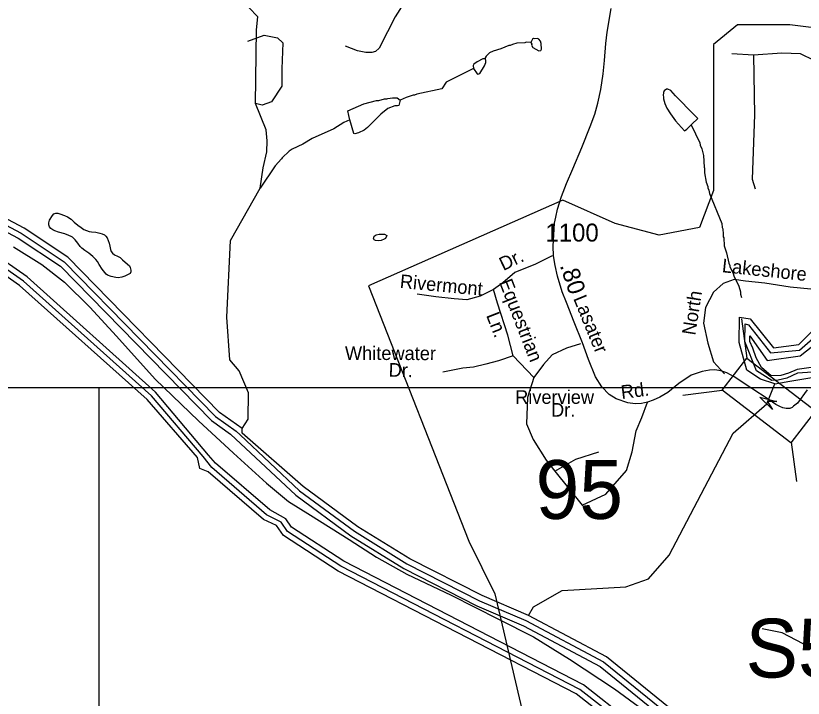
# Model space of a CAD drawing. Extents: x 1547597 to 1699558, y 810033 to 920809.
# Drawn here: x 1574920 to 1580417, y 829140 to 833901 of the extents above; entities that cross this region are included whole.
import ezdxf

# ---------------------------------------------------------------- set-up
doc = ezdxf.new("R2010")
doc.units = 0
for name, color, linetype in [('Exist Boundary Political City Limit New', 7, 'Continuous'), ('Exist Boundary Political CountyLine', 7, 'Continuous'), ('Exist Hydrographic Bay Label', 7, 'Continuous'), ('Exist Hydrographic Buffer Line', 7, 'Continuous'), ('Exist Hydrographic Creek Single Shore', 7, 'Continuous'), ('Exist Hydrographic Lake Shore', 7, 'Continuous'), ('Exist Hydrographic Misc Water Feature', 7, 'Continuous'), ('Exist Road Non-System Type 51', 7, 'Continuous'), ('Exist Road Non-System Type 51 Label', 7, 'Continuous'), ('Exist Road Primary Interstate Structure Ovrhead Sign Number Label', 7, 'Continuous'), ('Exist Road Secondary Mileage Hundredths English Label', 7, 'Continuous'), ('Exist Road Secondary Structure Standard Bridge Attributed CELL', 7, 'Continuous'), ('Exist Road Secondary Structure Standard Bridge CELL', 7, 'Continuous'), ('Exist Road Secondary Structure Standard Bridge Number Label', 7, 'Continuous'), ('Exist Road Secondary Type 51 Attributed', 7, 'Continuous'), ('Exist Road Secondary Type 51 Label', 7, 'Continuous'), ('Exist Road Secondary Type 51 Number Label', 7, 'Continuous'), ('Map Preparation Boundary City Limit Buffer Line', 7, 'Continuous'), ('Map Preparation Inset Cut Line', 7, 'Continuous')]:
    doc.layers.add(name, color=color, linetype=linetype)

msp = doc.modelspace()

# ---------------------------------------------------------------- linework, layer by layer
at = {"layer": 'Exist Boundary Political City Limit New'}
msp.add_lwpolyline([(1580658, 833796.5), (1580321.9, 833837.3), (1579957.7, 833837.3), (1579789.6, 833701.4), (1579789.6, 832682), (1579691.5, 832423.7), (1579411.4, 832369.4), (1579103.2, 832450.9), (1578739, 832614), (1577381.7, 832016), (1578082.1, 830235.4), (1578264.2, 829868.4), (1578460.3, 829033.8), (1578866.5, 827796.9), (1579062.6, 826940.6), (1579272.7, 826560), (1579538.9, 825894), (1580015.1, 826233.8), (1580561.4, 826641.6)], dxfattribs=at)
at = {"layer": 'Exist Boundary Political CountyLine'}
msp.add_lwpolyline([(1574903.6, 832288.8), (1575102.3, 832165.2), (1575261.2, 832041.5), (1575437.8, 831869.2), (1575623.2, 831666.1), (1575892.4, 831365.7), (1576197, 831074.2), (1576439.8, 830849), (1576669.4, 830641.4), (1576823.9, 830513.3), (1576978.4, 830416.1), (1577247.7, 830248.3), (1577437.5, 830124.6), (1577649.4, 830005.3), (1577958.4, 829859.6), (1578289.5, 829691.8), (1578534.5, 829568.1), (1578786.2, 829413.5), (1579099.6, 829205.9), (1579368.9, 829007.2)], dxfattribs=at)
at = {"layer": 'Exist Hydrographic Bay Label'}
for points in [[(1576500.5, 831022.5), (1576343.5, 831134), (1575283.5, 832215.8), (1574978.5, 832419), (1574167.5, 832849), (1573820.5, 833112.1), (1573485.5, 833516.1), (1573216.5, 833981.1), (1573152.5, 834162.9), (1573095.5, 834233.1), (1572740.5, 835060.9), (1572605.5, 835523.3), (1572580.5, 835540.2), (1572581.4, 835589.4), (1572371.5, 836049.9), (1572346.4, 836060.3), (1572330.5, 836119.7), (1572158.5, 836330), (1571821.5, 836658.5), (1571434.5, 836958.5), (1570908.5, 837497.8), (1570744.5, 837724.2)], [(1576204.5, 830743), (1576188.5, 830818.8), (1575836.5, 831223.1), (1574947.5, 832019.1), (1574699.5, 832191.6), (1574120.5, 832498.7), (1573815.4, 832728.1), (1573659.5, 832888.9), (1573080.5, 833757.4), (1572731.4, 834480.1), (1572529.5, 834864.9), (1572400.5, 835176.2), (1572409.5, 835208.8), (1572360.5, 835285.3), (1572353.5, 835383.9), (1572134.5, 835854.5), (1571963.5, 836091), (1571642.5, 836412.6), (1571132.4, 836843.2), (1570959.5, 837020.7), (1570893.5, 837048.3)], [(1578498.5, 829718.2), (1578175.5, 829856.1), (1577671.5, 830112.5), (1577307.5, 830336.5), (1576927.5, 830616.7), (1576499.5, 830989.7), (1576500.5, 831022.5)], [(1580668.5, 826375.2), (1580662.5, 826559.1), (1580637.5, 826592.5), (1580565.6, 827335.8), (1580330.6, 827832.9), (1580035.5, 828186.9), (1579780.5, 828408.7), (1579524.5, 828578), (1579146.5, 828923.9), (1578832.6, 829169.8), (1577169.5, 830027.5), (1576789.5, 830274.8), (1576740.5, 830344.7), (1576649.5, 830385.9), (1576262.5, 830718.8), (1576204.5, 830743)], [(1581965.5, 823873.7), (1581867.5, 824016.9), (1581706.6, 824378), (1581658.6, 824520.1), (1581561.5, 824722.3), (1581505.5, 824930.2), (1581481.5, 824947.2), (1581281.5, 825574.9), (1581208.5, 825717.5), (1581026.5, 826338.4), (1580929.5, 827157.8), (1580890.6, 827322.6), (1580647.6, 827852.8), (1580418.5, 828139.8), (1579786.6, 828825.5), (1579044.5, 829428.1), (1578498.5, 829718.2)]]:
    msp.add_lwpolyline(points, dxfattribs=at)
at = {"layer": 'Exist Hydrographic Buffer Line'}
for points in [[(1574119.2, 832785.3), (1574937.5, 832350.2), (1575232.2, 832153.8), (1576286.4, 831078), (1576420.2, 830981.4), (1576874.9, 830556.4), (1577260, 830272.1), (1577629.6, 830044.4), (1578139.2, 829784.8), (1578464, 829646), (1579000.1, 829361.1), (1579731.6, 828767.1)], [(1574143.3, 832817.1), (1574958, 832384.6), (1575257.9, 832184.9), (1576314.9, 831106), (1576459.9, 831002.3), (1576487.2, 830976.6), (1576901.3, 830586.5), (1577283.7, 830304.3), (1577650.6, 830078.4), (1578157.3, 829820.5), (1578481.3, 829682), (1579022.2, 829394.6), (1579759.1, 828796.3)], [(1579200.5, 828982.9), (1578881.9, 829232.8), (1577209.8, 830096.7), (1576846.1, 830333.3), (1576806, 830390.6), (1576692.9, 830454.1), (1576314.7, 830779.4), (1576266.7, 830835.3), (1575896.9, 831275.7), (1575001, 832078.7), (1574745.1, 832257.2)], [(1580198, 831356.6), (1580090.5, 831424.5), (1580008.6, 831628.1), (1580010.8, 831752.8), (1580034, 831745.5), (1580189.1, 831548.6), (1580390.6, 831567.3), (1580501.3, 831665), (1580877.9, 831641.1), (1580979.7, 831760.3), (1581012.9, 831926.1), (1580974.6, 832128.1), (1580976, 832227.9), (1581049.7, 832160.8), (1581086.4, 832039.6), (1581115.9, 831831.9)], [(1579173.5, 828953.4), (1578857.3, 829201.3), (1577189.6, 830062.1), (1576817.8, 830304), (1576773.3, 830367.7), (1576671.2, 830420), (1576288.6, 830749.1), (1576227.7, 830827.1), (1575866.7, 831249.4), (1574974.2, 832048.9), (1574722.4, 832224.4)], [(1580567.6, 831462.2), (1580373.4, 831432.9), (1580313.2, 831407.4), (1580259.6, 831392.2), (1580191.8, 831390.1), (1580125, 831446.5), (1580088.3, 831514.8), (1580063.8, 831581.4), (1580042.9, 831629.1), (1580042.9, 831667.9), (1580165.2, 831494.9), (1580395.8, 831527.6), (1580516, 831623.4)], [(1580585.3, 831421.4), (1580375.6, 831406.7), (1580301.4, 831373.3), (1580241.9, 831358.7), (1580198, 831356.6)]]:
    msp.add_lwpolyline(points, dxfattribs=at)
at = {"layer": 'Exist Hydrographic Creek Single Shore'}
for points in [[(1576500.5, 831022.5), (1576542.5, 831087.4), (1576545.5, 831271.1), (1576480.5, 831423.5), (1576415.5, 831500.2), (1576394.5, 831799.4), (1576419.5, 832334), (1576625.4, 832698.5), (1576646.4, 832841), (1576673.7, 832952.2), (1576675.7, 833028.2), (1576667.9, 833106.2), (1576593.2, 833289.3), (1576600.6, 833803.4), (1576610.3, 833893.1), (1576547.9, 833957.5), (1576498.7, 834080.8), (1576483.8, 834208.9)], [(1578498.5, 829718.2), (1578533.5, 829776.6), (1578734.5, 829890.7), (1579177.6, 829917.8), (1579336.6, 829973.7), (1579480.5, 830138.2), (1579926.5, 830989.3), (1580162.5, 831194.6), (1580218.9, 831333.6)]]:
    msp.add_lwpolyline(points, dxfattribs=at)
at = {"layer": 'Exist Hydrographic Lake Shore'}
for points in [[(1580218.9, 831333.6), (1580271.1, 831343), (1580308.7, 831350.4), (1580365.1, 831358.7), (1580475.7, 831376.5), (1580595.7, 831389), (1580838.6, 831259.6), (1581047.5, 831291.5), (1581301.5, 831519.5), (1581494.5, 831591.1), (1581710.6, 831590), (1581726.6, 831556.8), (1581918.5, 831536.5), (1582145.6, 831673.1), (1582306.5, 831863.5), (1582542.6, 832003.2), (1582751.5, 832074.4), (1582828.5, 832214), (1582980.6, 832378.3), (1582991.5, 832538.9)], [(1580218.9, 831333.6), (1580117.7, 831366), (1580023.7, 831427.7), (1579968.5, 831621.9), (1579971.5, 831799.2), (1580046.6, 831787.8), (1580209.5, 831584.3), (1580385.5, 831607), (1580486.5, 831706.6)]]:
    msp.add_lwpolyline(points, dxfattribs=at)
at = {"layer": 'Exist Hydrographic Misc Water Feature'}
for points in [[(1576539.4, 833724), (1576654.7, 833766.3), (1576746.9, 833747), (1576785.3, 833712.4), (1576777.7, 833531.7), (1576777.7, 833408.6), (1576704.6, 833300.9), (1576639.3, 833277.8), (1576593.2, 833289.3)], [(1578514.7, 833713.8), (1578482.7, 833716.2), (1578474.6, 833712.3), (1578418.7, 833709.1), (1578386.6, 833701.5), (1578370.5, 833693.7), (1578362.5, 833693.8), (1578306.2, 833670.5), (1578252.1, 833653.2), (1578227.9, 833641.5), (1578203.7, 833619.8), (1578195.5, 833607.9), (1578197.4, 833599.9)], [(1578514.7, 833713.8), (1578522.5, 833703.8), (1578520.5, 833695.8), (1578528.3, 833679.7), (1578570, 833655.2), (1578586, 833659), (1578590.1, 833666.9), (1578586.6, 833707), (1578582.8, 833723), (1578570.9, 833737.2), (1578563, 833741.3), (1578543, 833739.5), (1578535, 833741.6), (1578526.9, 833737.7), (1578514.7, 833713.8)], [(1578197.4, 833599.9), (1578181.4, 833600.1), (1578141.2, 833580.6), (1578117, 833562.9), (1578112.9, 833555), (1578114.3, 833532.3)], [(1578114.3, 833532.3), (1578140.2, 833496.7), (1578146.1, 833492.6), (1578160.2, 833498.4), (1578192.8, 833552), (1578201.1, 833575.9), (1578201.3, 833591.8), (1578197.4, 833599.9)], [(1578114.3, 833532.3), (1577925.5, 833437.4), (1577895, 833391.8), (1577718.6, 833354), (1577702.5, 833346.2), (1577694.5, 833346.3), (1577646.3, 833330.9), (1577604, 833313)], [(1579634.4, 833140.5), (1579639.6, 833144), (1579680.1, 833183.5), (1579654.4, 833209.8), (1579526, 833341.3), (1579492.5, 833379.7), (1579470.6, 833388), (1579462.6, 833388.1), (1579446.5, 833376.3), (1579440.3, 833366.4), (1579438.1, 833344.4), (1579442, 833336.4), (1579441.8, 833320.4), (1579449.5, 833288.3), (1579465, 833256.1), (1579490.6, 833215.8), (1579525.9, 833167.4), (1579588.9, 833098), (1579603.2, 833110.5), (1579634.4, 833140.5)], [(1577251.9, 833174.3), (1577244.9, 833204), (1577237.2, 833236.8), (1577349.8, 833286.7), (1577438.1, 833309.6), (1577454.1, 833309.4), (1577494.3, 833320.9), (1577510.3, 833320.6), (1577518.3, 833324.5), (1577550.3, 833328.1), (1577582.4, 833327.8), (1577604, 833313)], [(1577604, 833313), (1577593.6, 833275.6), (1577583.7, 833271.7), (1577565.6, 833272), (1577517.5, 833254.6), (1577469, 833215.2), (1577375.9, 833120.4), (1577351.7, 833102.7), (1577311.5, 833083.2), (1577287.4, 833077.6), (1577279.4, 833079.7), (1577251.9, 833174.3)], [(1577251.9, 833174.3), (1577210.4, 833156.5), (1577139.8, 833111.4), (1576989, 833045.3), (1576924.6, 833006.1), (1576850.2, 832971.1), (1576828.1, 832957.4), (1576779.5, 832910), (1576775.5, 832902.1), (1576730.9, 832854.7), (1576625.4, 832698.5)], [(1579634.4, 833140.5), (1579694.1, 833013.4), (1579697.9, 832997.3), (1579709.7, 832973.2), (1579721, 832925), (1579724.1, 832845), (1579728, 832837), (1579727.6, 832805), (1579738.9, 832740.9), (1579750.5, 832708.8), (1579750.4, 832700.8), (1579758.2, 832684.7), (1579762, 832660.6), (1579847.5, 832451.7), (1579851, 832423.6), (1579854.9, 832415.6), (1579854.8, 832399.6), (1579858.7, 832391.6), (1579858.3, 832359.6), (1579862.2, 832351.5), (1579865.6, 832295.5), (1579881, 832247.4), (1579896.2, 832175.2), (1579904, 832159.1), (1579903.8, 832151.1), (1579927.2, 832102.8), (1579931.1, 832086.8), (1579966.2, 832014.4), (1579977.8, 831974.3), (1579977.6, 831958.3), (1579984.7, 831936.5)], [(1575542, 832109), (1575524.1, 832133.5), (1575503.1, 832165.9), (1575490.4, 832186.4), (1575478.9, 832201), (1575457.7, 832221.6), (1575430.6, 832243.6), (1575403.6, 832264.4), (1575381, 832280.5), (1575369.4, 832291.7), (1575354.8, 832313.6), (1575334.3, 832338.1), (1575316.3, 832355.4), (1575306.6, 832361.5), (1575291.1, 832368.9), (1575263.1, 832378.6), (1575218.9, 832391.8), (1575193, 832400.7), (1575179.3, 832407.5), (1575166.4, 832416.9), (1575156.9, 832428.2), (1575151.3, 832442.7), (1575150.8, 832456.4), (1575157, 832475.8), (1575176.5, 832508.2), (1575187.1, 832518.4), (1575199.6, 832522.8), (1575214, 832523.1), (1575229, 832520.3), (1575260.1, 832508.6), (1575280.8, 832497.1), (1575306.1, 832481), (1575329.2, 832461), (1575354.4, 832440.3), (1575376.9, 832422.9), (1575396.3, 832410.8), (1575415.1, 832402.6), (1575432, 832396.4), (1575448.3, 832393.5), (1575479.5, 832390.3), (1575506.2, 832385.3), (1575524.4, 832379.1), (1575538.7, 832371.7), (1575549, 832363.6), (1575557.3, 832351.7), (1575566.1, 832333.9), (1575572.9, 832313.5), (1575577.9, 832293.2), (1575582.7, 832270.3), (1575587, 832257.1), (1575595.9, 832244.5), (1575609.4, 832233.9), (1575629.5, 832223.7), (1575649.6, 832213.5), (1575665.7, 832198.9), (1575700.4, 832166.9), (1575713.3, 832155.6), (1575718.9, 832144.4), (1575723.9, 832125.3), (1575723, 832114.9), (1575718.3, 832103.9), (1575705.7, 832095.6), (1575682, 832083.6), (1575659.7, 832076.2), (1575634.8, 832073.4), (1575617.9, 832074.3), (1575585.3, 832082.8), (1575560.6, 832092.4), (1575551, 832099), (1575542, 832109)], [(1577456, 832377), (1577495, 832377.3), (1577510.9, 832367.1), (1577500.6, 832347.2), (1577492.6, 832341.3), (1577470.5, 832333.6), (1577454.5, 832331.8), (1577430.5, 832334.1), (1577422.6, 832338.2), (1577416.7, 832346.3), (1577420.9, 832362.2), (1577435, 832372), (1577456, 832377)]]:
    msp.add_lwpolyline(points, dxfattribs=at)
at = {"layer": 'Exist Road Non-System Type 51'}
for points in [[(1580069.4, 833625.7), (1579917.2, 833634.6)], [(1580069.4, 833625.7), (1580075.4, 833210.3), (1580060.5, 832762.1), (1580081.4, 832693.4)], [(1580645.6, 833356.7), (1580577, 833506.1), (1580493.4, 833589.8), (1580397.8, 833634.6), (1580266.5, 833640.6), (1580069.4, 833625.7)], [(1578664.5, 832227.3), (1578548.8, 832166.9), (1578404.5, 832110.2), (1578319.5, 832038), (1578255, 831990.2)], [(1580620.9, 832077.3), (1580538.3, 832016.8), (1580469.5, 831993.9), (1580324.3, 832006.6), (1580148.5, 832034.7), (1580013.5, 832050), (1579934.5, 832060.2), (1579858.1, 832032.1), (1579789.3, 831973.5), (1579733.2, 831866.4), (1579720.5, 831756.7), (1579751.1, 831616.5), (1579789.3, 831486.5), (1579866.7, 831403.9)], [(1578255, 831990.2), (1578162.4, 831945.1), (1578069.6, 831919.4), (1577979.4, 831927.1), (1577853.2, 831940), (1577721.8, 831958)], [(1578391.6, 831529.5), (1578355.5, 831673), (1578283.3, 831894.8), (1578255, 831990.2)], [(1578862.5, 831613.4), (1578765.1, 831581.1), (1578664.7, 831534.7), (1578602.8, 831467.7), (1578535.9, 831377.4)], [(1578391.6, 831529.5), (1578288.5, 831493.4), (1578200.9, 831470.2), (1578115.9, 831449.6), (1578041.2, 831441.9), (1577902.1, 831413.5)], [(1578535.9, 831377.4), (1578391.6, 831529.5)], [(1578535.9, 831377.4), (1578492.1, 831238.2), (1578484.3, 831055.1), (1578530.7, 830944.2), (1578623.4, 830799.9), (1578682.7, 830725.1)], [(1578873.4, 830487.9), (1579038.2, 830562.6), (1579182.5, 830727.7), (1579223.7, 830859.2), (1579249.5, 831006.1), (1579290.7, 831098.9), (1579330.2, 831204.2)], [(1578682.7, 830725.1), (1578829.6, 830807.6), (1578989.3, 830859.2)], [(1578682.7, 830725.1), (1578873.4, 830487.9)], [(1581649.4, 829981.3), (1581519.6, 829950.9), (1581424.4, 829944.9), (1581341.1, 829912.2), (1581132.9, 829843.7), (1580951.5, 829772.2), (1580743.3, 829641.3), (1580621.3, 829557.9), (1580535.1, 829522.2), (1580416.1, 829519.2), (1580270.3, 829596.6), (1580130.5, 829623.4)]]:
    msp.add_lwpolyline(points, dxfattribs=at)
at = {"layer": 'Exist Road Secondary Structure Standard Bridge Attributed CELL'}
msp.add_lwpolyline([(1580201.8, 831155.2), (1580114.3, 831240.1), (1580232.5, 831210.3), (1580167.5, 831210.4)], close=True, dxfattribs=at)
at = {"layer": 'Exist Road Secondary Structure Standard Bridge CELL'}
for p, q in [((1579985.8, 831786.8), (1580021.8, 831513.2)), ((1579576.3, 831253.1), (1579849.9, 831289.1)), ((1580332.5, 830925.2), (1580368.5, 830651.6))]:
    msp.add_line(p, q, dxfattribs=at)
msp.add_lwpolyline([(1580021.8, 831513.2), (1580501.3, 831145.2), (1580329.4, 830921.2), (1579849.9, 831289.1)], close=True, dxfattribs=at)
at = {"layer": 'Exist Road Secondary Type 51 Attributed'}
for points in [[(1579107.5, 834074.1), (1578835.3, 834156.6), (1578609.9, 834214.3), (1578461.2, 834223.9), (1578254.9, 834195.1), (1577964.7, 834152.5), (1577756, 834109.6), (1577669.7, 834046.2), (1577645.8, 834017.4), (1577568.8, 833893.1), (1577514.2, 833789.8), (1577457.1, 833675.9), (1577431.3, 833651.3), (1577406, 833645.4), (1577363.1, 833645.4), (1577304.6, 833657.1), (1577222.7, 833688.3)], [(1580172.2, 831225.1), (1580057.2, 831299.6), (1579933.3, 831381.5), (1579883.7, 831410.4), (1579841.6, 831424.2), (1579799.9, 831429.8), (1579762.8, 831428.5), (1579710.5, 831420.1), (1579635.3, 831394.6), (1579548.5, 831334.5), (1579471, 831273.4), (1579416.7, 831239.2), (1579369.7, 831218.5), (1579330.2, 831204.2), (1579288.2, 831195.8), (1579243.2, 831194.8), (1579191.6, 831201.4), (1579111.1, 831228), (1579062.5, 831258.9), (1579009.9, 831312.1), (1578967.2, 831381.8), (1578918.6, 831503.1), (1578875.8, 831618.4), (1578818, 831763), (1578764.4, 831900.7), (1578733.9, 831974.9), (1578701, 832085), (1578684.3, 832158), (1578674.4, 832225.3), (1578671.4, 832293.7), (1578674.4, 832334.1), (1578678, 832412.3), (1578681, 832453.4), (1578690.1, 832496.8), (1578701.7, 832552.4), (1578729, 832640), (1578764.4, 832729.8), (1578809.5, 832833.6), (1578871.2, 832981.8), (1578930.4, 833128.7), (1578962.9, 833213.5), (1578983.6, 833292.3), (1579003.3, 833387.3), (1579019.4, 833495.4), (1579029, 833588.7), (1579039.2, 833706.4), (1579048, 833786.9), (1579076, 833950.5)], [(1580443.8, 831290.4), (1580376.6, 831197.4), (1580348.7, 831176.7), (1580339.5, 831168.5), (1580322.4, 831162.3), (1580297.7, 831161), (1580273.4, 831165.2), (1580253.7, 831174.4), (1580225.4, 831188.9), (1580172.2, 831225.1)]]:
    msp.add_lwpolyline(points, dxfattribs=at)
at = {"layer": 'Map Preparation Boundary City Limit Buffer Line'}
msp.add_lwpolyline([(1580658, 833796.5), (1580321.9, 833837.3), (1579957.7, 833837.3), (1579789.6, 833701.4), (1579789.6, 832682), (1579691.5, 832423.7), (1579411.4, 832369.4), (1579103.2, 832450.9), (1578739, 832614), (1577381.7, 832016), (1578082.1, 830235.4), (1578264.2, 829868.4), (1578460.3, 829033.8), (1578866.5, 827796.9), (1579062.6, 826940.6), (1579272.7, 826560), (1579538.9, 825894), (1580015.1, 826233.8), (1580561.4, 826641.6)], dxfattribs=at)
at = {"layer": 'Map Preparation Inset Cut Line'}
for points in [[(1633724, 874749.3), (1571208, 874749.3), (1571208, 831307.2), (1633724, 831307.2)], [(1575502.6, 831307.2), (1641328.6, 831307.2), (1641328.6, 811336.3), (1575502.6, 811336.3)]]:
    msp.add_lwpolyline(points, close=True, dxfattribs=at)

# ---------------------------------------------------------------- texts
at = {"layer": 'Exist Road Non-System Type 51 Label'}
for s, rotation, p in [('Dr.', 25.8921, (1578323.7, 832119.3)), ('Lakeshore', 353.9567, (1579846.4, 832112.4)), ('Rivermont', 354.5142, (1577598.4, 832003.1)), ('Equestrian', 291.2895, (1578292.4, 832042.7)), ('North', 81.0844, (1579662.6, 831668.2)), ('Ln.', 291.2895, (1578201.9, 831811.5)), ('Whitewater', 359.8314, (1577217.8, 831500.3)), ('Dr.', 358.3481, (1577522, 831384.1))]:
    msp.add_text(s, height=95, rotation=rotation, dxfattribs=at).set_placement(p)
for s, p in [('Riverview', (1578405.8, 831193.6)), ('Dr.', (1578656.2, 831104.2))]:
    msp.add_text(s, height=95, dxfattribs=at).set_placement(p)
at = {"layer": 'Exist Road Primary Interstate Structure Ovrhead Sign Number Label'}
msp.add_text('S583', height=410.1, dxfattribs=at).set_placement((1580014.1, 829284.4))
at = {"layer": 'Exist Road Secondary Mileage Hundredths English Label'}
msp.add_text('.80', height=120, rotation=288.4206, dxfattribs=at).set_placement((1578716.6, 832158.3))
at = {"layer": 'Exist Road Secondary Structure Standard Bridge Number Label'}
msp.add_text('95', height=410.1, dxfattribs=at).set_placement((1578548.4, 830391))
at = {"layer": 'Exist Road Secondary Type 51 Label'}
for s, rotation, p in [('Lasater', 292.2986, (1578809.9, 831928.9)), ('Rd.', 7.1999, (1579149.7, 831227.1))]:
    msp.add_text(s, height=95, rotation=rotation, dxfattribs=at).set_placement(p)
at = {"layer": 'Exist Road Secondary Type 51 Number Label'}
msp.add_text('1100', height=125, dxfattribs=at).set_placement((1578617.2, 832326))

doc.saveas('drawing.dxf')
